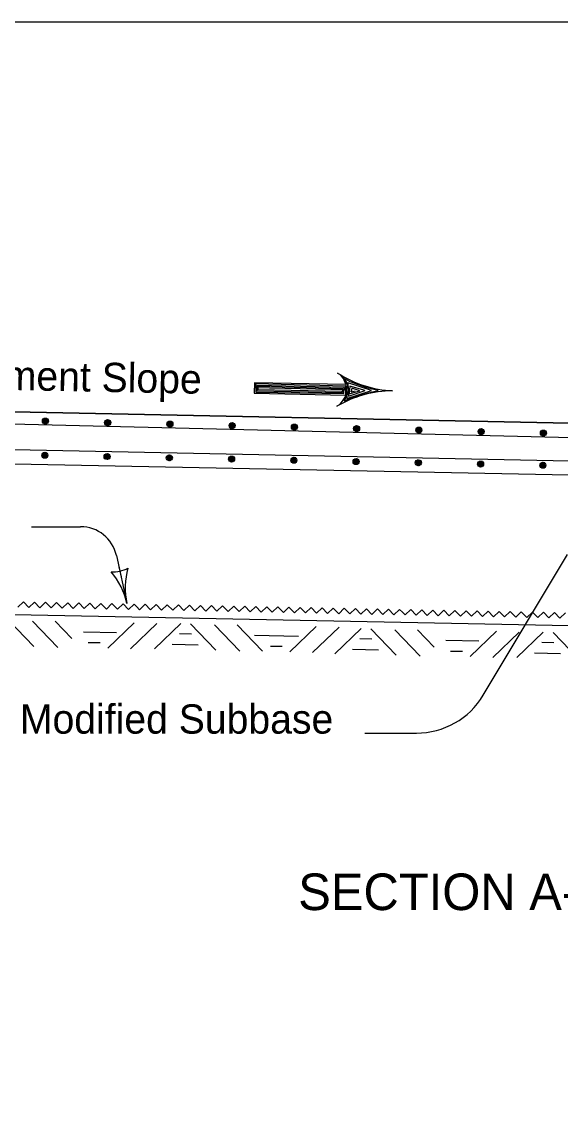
# Model space of a CAD drawing. Extents: x 9234 to 81668, y 5635 to 15999.
# Drawn here: x 17675 to 17970, y 9343 to 9944 of the extents above; entities that cross this region are included whole.
import ezdxf

# ---------------------------------------------------------------- set-up
doc = ezdxf.new("R2010")
doc.units = 0
for name, color, linetype in [('Level 61', 7, 'Continuous'), ('PS_BOLT', 7, 'Continuous'), ('PS_CONST', 7, 'Continuous'), ('PS_DIM', 7, 'Continuous')]:
    doc.layers.add(name, color=color, linetype=linetype)

msp = doc.modelspace()

# ---------------------------------------------------------------- linework, layer by layer
at = {"layer": 'Level 61'}
msp.add_lwpolyline([(17332.52, 9944.02), (20467.53, 9944.02), (20467.53, 7924.02), (17332.52, 7924.02)], close=True, dxfattribs=at)
at = {"layer": 'PS_BOLT'}
msp.add_line((18198.1, 9699.22), (17466.58, 9714.38), dxfattribs=at)
at = {"layer": 'PS_CONST'}
for p, q in [((17852.17, 9745.92), (17852.17, 9745.92)), ((17852.26, 9742.89), (17802.12, 9743.9)), ((17852.11, 9740.06), (17852.11, 9740.06)), ((17680.34, 9668.04), (17707.15, 9668.04)), ((17726.68, 9652.34), (17732.49, 9625.97)), ((17927.27, 9575.92), (17973.29, 9652.89)), ((17862.47, 9555.21), (17890.76, 9555.21))]:
    msp.add_line(p, q, dxfattribs=at)
for points in [[(17852.22, 9745.73), (17802.18, 9746.74), (17802.06, 9741.07), (17852.11, 9740.06), (17852.04, 9744.92), (17802.81, 9746.1), (17802.85, 9741.58), (17851.02, 9740.8), (17851.21, 9744.18), (17803.49, 9745.33), (17803.55, 9742.32), (17850.4, 9741.38), (17850.57, 9743.5), (17804.04, 9744.69), (17804.07, 9743), (17849.79, 9742.14)], [(17850.94, 9749.45), (17853, 9746.03), (17853.16, 9741.07), (17851.25, 9736.79), (17858.71, 9739.71), (17867.4, 9742.04), (17869.85, 9742.56), (17863.61, 9743.93), (17854.6, 9747.25), (17851.93, 9748.74), (17852.72, 9738.2), (17866.15, 9742.44), (17853.2, 9746.65), (17853.56, 9739.37), (17862.77, 9742.57), (17854.42, 9744.81), (17853.96, 9740.62), (17859.83, 9742.38), (17855.4, 9743.72), (17855.11, 9741.72), (17857.25, 9742.31)]]:
    msp.add_lwpolyline(points, dxfattribs=at)
for centre, radius, start, end in [((17841.88, 9743.1), 10.67, 300.56474, 57.13538), ((17880.75, 9803.26), 60.95, 237.1358, 267.16583), ((17878.3, 9681.43), 60.95, 90.53429, 120.56432), ((17707.15, 9648.04), 20, 12.43142, 90), ((17725.25, 9658.87), 15.52, 264.68499, 300.15169), ((17693.26, 9617.33), 40.18, 12.41834, 40.49083), ((17771.73, 9634.61), 40.18, 164.34585, 192.41834), ((17890.76, 9597.75), 42.54, 270, 329.12488)]:
    msp.add_arc(centre, radius, start, end, dxfattribs=at)
at = {"layer": 'PS_DIM'}
for p, q in [((18176.88, 9720.67), (17466.62, 9734.93)), ((17466.62, 9734.93), (18176.88, 9720.67)), ((17466.59, 9729.18), (18198.18, 9711.52)), ((17466.05, 9706.58), (18215.16, 9691.54)), ((17467.19, 9706.55), (18215.16, 9691.54)), ((17728.1, 9645.89), (17729.23, 9640.78)), ((17466.62, 9624.14), (18283.21, 9607.75)), ((17667.77, 9616.94), (17681.63, 9602.52)), ((17680.77, 9616.45), (17694.63, 9602.03)), ((17693.23, 9616.43), (17702.33, 9606.95)), ((17736.44, 9615.56), (17722.02, 9601.7)), ((17748.88, 9615.08), (17734.46, 9601.23)), ((17761.89, 9615.05), (17747.47, 9601.19)), ((17767.3, 9614.94), (17781.16, 9600.52)), ((17780.31, 9614.45), (17794.16, 9600.03)), ((17792.76, 9614.43), (17806.61, 9600.01)), ((17835.97, 9613.56), (17821.55, 9599.71)), ((17848.42, 9613.09), (17833.99, 9599.23)), ((17860.46, 9612.33), (17846.04, 9598.47)), ((17865.87, 9612.22), (17879.73, 9597.8)), ((17878.88, 9611.73), (17892.73, 9597.31)), ((17891.33, 9611.71), (17900.43, 9602.24)), ((17934.54, 9610.84), (17920.12, 9596.99)), ((17946.99, 9610.37), (17932.56, 9596.51)), ((17960, 9610.33), (17945.57, 9596.48)), ((17965.41, 9610.22), (17979.26, 9595.8))]:
    msp.add_line(p, q, dxfattribs=at)
for points in [[(17686.37, 9725.74), (17686.65, 9726.29), (17686.95, 9727.14), (17687.84, 9727.27), (17688.61, 9727.12), (17689.3, 9726.53), (17689.19, 9725.71), (17689.03, 9724.84), (17688.32, 9724.45), (17687.58, 9724.41), (17686.65, 9724.97), (17686.6, 9725.61), (17686.86, 9726.47), (17687.44, 9727.16), (17688.27, 9727.1), (17688.91, 9726.51), (17688.95, 9725.73), (17688.74, 9724.87), (17688.24, 9724.76), (17687.65, 9724.6), (17686.95, 9725.05), (17686.99, 9725.68), (17687.15, 9726.4), (17687.57, 9726.9), (17688.28, 9726.61), (17688.68, 9726.04), (17688.68, 9725.31), (17688.27, 9725.15), (17687.82, 9724.93), (17687.26, 9725.32), (17687.15, 9725.86), (17687.44, 9726.33), (17687.97, 9726.34), (17688.34, 9726.07), (17688.45, 9725.57), (17688.24, 9725.34), (17687.94, 9725.22), (17687.52, 9725.49), (17687.45, 9725.84), (17687.67, 9726.17), (17687.95, 9726.09), (17688.13, 9725.84), (17688.1, 9725.5), (17687.86, 9725.51), (17687.74, 9725.82)], [(17720.4, 9724.92), (17720.68, 9725.47), (17720.98, 9726.32), (17721.87, 9726.45), (17722.64, 9726.3), (17723.33, 9725.71), (17723.22, 9724.89), (17723.06, 9724.02), (17722.35, 9723.64), (17721.61, 9723.59), (17720.68, 9724.15), (17720.63, 9724.79), (17720.89, 9725.65), (17721.47, 9726.33), (17722.3, 9726.27), (17722.94, 9725.69), (17722.98, 9724.91), (17722.77, 9724.05), (17722.27, 9723.93), (17721.68, 9723.78), (17720.98, 9724.22), (17721.02, 9724.85), (17721.17, 9725.57), (17721.6, 9726.08), (17722.31, 9725.78), (17722.71, 9725.22), (17722.71, 9724.49), (17722.3, 9724.32), (17721.85, 9724.11), (17721.29, 9724.49), (17721.18, 9725.04), (17721.46, 9725.51), (17722, 9725.51), (17722.37, 9725.24), (17722.48, 9724.75), (17722.27, 9724.52), (17721.97, 9724.39), (17721.55, 9724.67), (17721.48, 9725.02), (17721.69, 9725.34), (17721.98, 9725.27), (17722.16, 9725.01), (17722.13, 9724.68), (17721.89, 9724.69), (17721.77, 9724.99)], [(17754.44, 9724.1), (17754.71, 9724.64), (17755.01, 9725.5), (17755.9, 9725.63), (17756.67, 9725.48), (17757.36, 9724.89), (17757.25, 9724.07), (17757.09, 9723.2), (17756.38, 9722.81), (17755.64, 9722.77), (17754.71, 9723.33), (17754.66, 9723.97), (17754.92, 9724.83), (17755.5, 9725.51), (17756.33, 9725.45), (17756.97, 9724.87), (17757.01, 9724.09), (17756.8, 9723.22), (17756.31, 9723.12), (17755.71, 9722.96), (17755.01, 9723.4), (17755.05, 9724.03), (17755.2, 9724.76), (17755.63, 9725.26), (17756.34, 9724.96), (17756.74, 9724.4), (17756.73, 9723.66), (17756.33, 9723.5), (17755.88, 9723.29), (17755.32, 9723.67), (17755.22, 9724.22), (17755.49, 9724.68), (17756.03, 9724.69), (17756.4, 9724.42), (17756.51, 9723.93), (17756.29, 9723.7), (17756, 9723.57), (17755.58, 9723.85), (17755.51, 9724.2), (17755.73, 9724.52), (17756.01, 9724.45), (17756.19, 9724.2), (17756.16, 9723.85), (17755.92, 9723.87), (17755.8, 9724.18)], [(17788.47, 9723.28), (17788.74, 9723.82), (17789.04, 9724.68), (17789.93, 9724.81), (17790.7, 9724.65), (17791.39, 9724.07), (17791.28, 9723.24), (17791.12, 9722.38), (17790.41, 9722), (17789.67, 9721.95), (17788.74, 9722.5), (17788.69, 9723.14), (17788.95, 9724), (17789.53, 9724.69), (17790.36, 9724.63), (17791, 9724.05), (17791.04, 9723.26), (17790.83, 9722.4), (17790.34, 9722.29), (17789.74, 9722.14), (17789.04, 9722.58), (17789.08, 9723.21), (17789.23, 9723.93), (17789.66, 9724.44), (17790.37, 9724.14), (17790.77, 9723.58), (17790.76, 9722.84), (17790.36, 9722.68), (17789.91, 9722.47), (17789.35, 9722.85), (17789.24, 9723.4), (17789.52, 9723.86), (17790.06, 9723.87), (17790.43, 9723.6), (17790.54, 9723.1), (17790.33, 9722.87), (17790.03, 9722.75), (17789.6, 9723.02), (17789.54, 9723.37), (17789.75, 9723.7), (17790.04, 9723.63), (17790.22, 9723.37), (17790.19, 9723.03), (17789.95, 9723.05), (17789.83, 9723.35)], [(17822.49, 9722.45), (17822.77, 9723), (17823.07, 9723.86), (17823.96, 9723.99), (17824.73, 9723.83), (17825.42, 9723.25), (17825.31, 9722.43), (17825.15, 9721.56), (17824.44, 9721.17), (17823.7, 9721.13), (17822.77, 9721.68), (17822.72, 9722.32), (17822.98, 9723.18), (17823.56, 9723.87), (17824.39, 9723.81), (17825.03, 9723.22), (17825.07, 9722.44), (17824.86, 9721.58), (17824.37, 9721.47), (17823.77, 9721.32), (17823.07, 9721.76), (17823.11, 9722.39), (17823.26, 9723.11), (17823.69, 9723.62), (17824.4, 9723.32), (17824.8, 9722.75), (17824.79, 9722.02), (17824.39, 9721.86), (17823.94, 9721.65), (17823.38, 9722.03), (17823.27, 9722.58), (17823.55, 9723.04), (17824.09, 9723.05), (17824.46, 9722.78), (17824.57, 9722.29), (17824.35, 9722.06), (17824.06, 9721.93), (17823.64, 9722.21), (17823.56, 9722.56), (17823.78, 9722.88), (17824.07, 9722.81), (17824.25, 9722.55), (17824.22, 9722.21), (17823.98, 9722.23), (17823.85, 9722.53)], [(17856.52, 9721.64), (17856.79, 9722.18), (17857.1, 9723.04), (17857.99, 9723.16), (17858.76, 9723.01), (17859.45, 9722.43), (17859.34, 9721.6), (17859.18, 9720.74), (17858.47, 9720.35), (17857.73, 9720.31), (17856.8, 9720.86), (17856.75, 9721.5), (17857, 9722.36), (17857.59, 9723.05), (17858.42, 9722.99), (17859.06, 9722.41), (17859.1, 9721.62), (17858.89, 9720.76), (17858.39, 9720.65), (17857.8, 9720.49), (17857.1, 9720.94), (17857.14, 9721.57), (17857.29, 9722.29), (17857.72, 9722.79), (17858.43, 9722.5), (17858.82, 9721.93), (17858.82, 9721.2), (17858.42, 9721.04), (17857.97, 9720.82), (17857.41, 9721.21), (17857.3, 9721.75), (17857.58, 9722.22), (17858.12, 9722.23), (17858.49, 9721.96), (17858.6, 9721.46), (17858.39, 9721.23), (17858.09, 9721.11), (17857.66, 9721.38), (17857.59, 9721.73), (17857.81, 9722.06), (17858.1, 9721.99), (17858.28, 9721.73), (17858.25, 9721.39), (17858.01, 9721.41), (17857.88, 9721.71)], [(17890.55, 9720.81), (17890.83, 9721.36), (17891.13, 9722.21), (17892.02, 9722.35), (17892.79, 9722.19), (17893.48, 9721.61), (17893.37, 9720.78), (17893.21, 9719.92), (17892.5, 9719.53), (17891.76, 9719.49), (17890.83, 9720.04), (17890.78, 9720.68), (17891.03, 9721.54), (17891.63, 9722.23), (17892.44, 9722.17), (17893.09, 9721.58), (17893.12, 9720.8), (17892.92, 9719.94), (17892.42, 9719.83), (17891.83, 9719.68), (17891.13, 9720.12), (17891.17, 9720.75), (17891.32, 9721.47), (17891.75, 9721.98), (17892.46, 9721.68), (17892.85, 9721.11), (17892.85, 9720.38), (17892.45, 9720.22), (17892, 9720.01), (17891.44, 9720.39), (17891.33, 9720.93), (17891.61, 9721.4), (17892.15, 9721.41), (17892.52, 9721.14), (17892.63, 9720.64), (17892.42, 9720.41), (17892.12, 9720.29), (17891.69, 9720.56), (17891.62, 9720.91), (17891.84, 9721.24), (17892.13, 9721.17), (17892.31, 9720.91), (17892.28, 9720.57), (17892.04, 9720.59), (17891.91, 9720.89)], [(17924.58, 9719.99), (17924.86, 9720.54), (17925.16, 9721.39), (17926.05, 9721.52), (17926.82, 9721.37), (17927.51, 9720.78), (17927.4, 9719.96), (17927.24, 9719.09), (17926.53, 9718.71), (17925.79, 9718.66), (17924.86, 9719.22), (17924.81, 9719.86), (17925.06, 9720.72), (17925.65, 9721.4), (17926.47, 9721.35), (17927.11, 9720.76), (17927.15, 9719.98), (17926.95, 9719.11), (17926.45, 9719.01), (17925.86, 9718.85), (17925.16, 9719.29), (17925.2, 9719.93), (17925.35, 9720.65), (17925.78, 9721.15), (17926.49, 9720.86), (17926.89, 9720.29), (17926.88, 9719.56), (17926.48, 9719.39), (17926.03, 9719.18), (17925.47, 9719.56), (17925.36, 9720.11), (17925.64, 9720.58), (17926.18, 9720.59), (17926.55, 9720.32), (17926.66, 9719.82), (17926.44, 9719.59), (17926.14, 9719.47), (17925.72, 9719.74), (17925.66, 9720.09), (17925.87, 9720.41), (17926.16, 9720.34), (17926.34, 9720.09), (17926.31, 9719.75), (17926.07, 9719.76), (17925.95, 9720.07)], [(17958.61, 9719.17), (17958.88, 9719.72), (17959.19, 9720.57), (17960.08, 9720.7), (17960.85, 9720.55), (17961.54, 9719.96), (17961.43, 9719.14), (17961.26, 9718.27), (17960.55, 9717.89), (17959.82, 9717.84), (17958.88, 9718.4), (17958.84, 9719.04), (17959.09, 9719.89), (17959.68, 9720.59), (17960.5, 9720.52), (17961.14, 9719.94), (17961.18, 9719.16), (17960.98, 9718.29), (17960.48, 9718.18), (17959.89, 9718.04), (17959.19, 9718.47), (17959.23, 9719.1), (17959.38, 9719.83), (17959.81, 9720.33), (17960.52, 9720.03), (17960.91, 9719.47), (17960.91, 9718.74), (17960.51, 9718.57), (17960.06, 9718.36), (17959.5, 9718.74), (17959.39, 9719.29), (17959.67, 9719.76), (17960.21, 9719.76), (17960.58, 9719.49), (17960.69, 9719), (17960.48, 9718.77), (17960.17, 9718.64), (17959.75, 9718.92), (17959.68, 9719.27), (17959.9, 9719.59), (17960.19, 9719.53), (17960.37, 9719.27), (17960.34, 9718.93), (17960.1, 9718.95), (17959.97, 9719.25)], [(17689.11, 9706.96), (17688.85, 9707.53), (17688.58, 9708.39), (17687.71, 9708.56), (17686.93, 9708.44), (17686.22, 9707.88), (17686.29, 9707.06), (17686.41, 9706.19), (17687.11, 9705.77), (17687.84, 9705.69), (17688.79, 9706.21), (17688.88, 9706.84), (17688.66, 9707.71), (17688.1, 9708.43), (17687.27, 9708.4), (17686.61, 9707.85), (17686.53, 9707.07), (17686.7, 9706.2), (17687.2, 9706.06), (17687.79, 9705.89), (17688.5, 9706.29), (17688.48, 9706.93), (17688.37, 9707.65), (17687.96, 9708.18), (17687.24, 9707.91), (17686.81, 9707.37), (17686.79, 9706.64), (17687.18, 9706.45), (17687.63, 9706.22), (17688.2, 9706.58), (17688.33, 9707.12), (17688.08, 9707.6), (17687.54, 9707.63), (17687.16, 9707.38), (17687.02, 9706.88), (17687.23, 9706.65), (17687.52, 9706.51), (17687.95, 9706.76), (17688.04, 9707.11), (17687.84, 9707.44), (17687.55, 9707.39), (17687.36, 9707.14), (17687.37, 9706.8), (17687.61, 9706.8), (17687.75, 9707.1)], [(17723.14, 9706.28), (17722.89, 9706.84), (17722.62, 9707.71), (17721.74, 9707.88), (17720.97, 9707.76), (17720.25, 9707.2), (17720.32, 9706.37), (17720.44, 9705.5), (17721.14, 9705.09), (17721.87, 9705.01), (17722.83, 9705.52), (17722.91, 9706.16), (17722.69, 9707.03), (17722.13, 9707.74), (17721.31, 9707.72), (17720.64, 9707.16), (17720.57, 9706.38), (17720.74, 9705.51), (17721.23, 9705.38), (17721.82, 9705.2), (17722.53, 9705.61), (17722.52, 9706.24), (17722.4, 9706.97), (17721.99, 9707.49), (17721.27, 9707.23), (17720.85, 9706.68), (17720.82, 9705.95), (17721.22, 9705.77), (17721.66, 9705.54), (17722.24, 9705.9), (17722.36, 9706.43), (17722.11, 9706.91), (17721.57, 9706.95), (17721.19, 9706.7), (17721.06, 9706.2), (17721.26, 9705.96), (17721.56, 9705.83), (17721.99, 9706.08), (17722.07, 9706.43), (17721.87, 9706.76), (17721.58, 9706.7), (17721.39, 9706.46), (17721.4, 9706.11), (17721.65, 9706.12), (17721.78, 9706.42)], [(17757.17, 9705.6), (17756.92, 9706.16), (17756.65, 9707.02), (17755.77, 9707.19), (17755, 9707.07), (17754.28, 9706.52), (17754.36, 9705.69), (17754.48, 9704.82), (17755.17, 9704.4), (17755.9, 9704.33), (17756.86, 9704.84), (17756.94, 9705.47), (17756.72, 9706.34), (17756.16, 9707.06), (17755.34, 9707.03), (17754.67, 9706.48), (17754.6, 9705.7), (17754.77, 9704.83), (17755.26, 9704.69), (17755.85, 9704.52), (17756.57, 9704.93), (17756.55, 9705.56), (17756.43, 9706.29), (17756.03, 9706.81), (17755.3, 9706.55), (17754.88, 9706), (17754.86, 9705.27), (17755.25, 9705.09), (17755.69, 9704.85), (17756.27, 9705.21), (17756.4, 9705.75), (17756.14, 9706.23), (17755.6, 9706.26), (17755.22, 9706.01), (17755.09, 9705.52), (17755.29, 9705.28), (17755.59, 9705.14), (17756.02, 9705.4), (17756.1, 9705.74), (17755.9, 9706.08), (17755.61, 9706.02), (17755.42, 9705.77), (17755.43, 9705.43), (17755.68, 9705.44), (17755.81, 9705.73)], [(17791.2, 9704.91), (17790.95, 9705.47), (17790.69, 9706.34), (17789.8, 9706.51), (17789.03, 9706.39), (17788.31, 9705.84), (17788.39, 9705.01), (17788.51, 9704.13), (17789.2, 9703.72), (17789.94, 9703.64), (17790.9, 9704.16), (17790.97, 9704.79), (17790.76, 9705.66), (17790.2, 9706.37), (17789.38, 9706.35), (17788.71, 9705.8), (17788.64, 9705.02), (17788.8, 9704.15), (17789.29, 9704.01), (17789.88, 9703.83), (17790.6, 9704.25), (17790.58, 9704.88), (17790.47, 9705.6), (17790.06, 9706.13), (17789.34, 9705.86), (17788.92, 9705.31), (17788.89, 9704.58), (17789.28, 9704.4), (17789.73, 9704.17), (17790.3, 9704.53), (17790.43, 9705.07), (17790.17, 9705.55), (17789.64, 9705.58), (17789.26, 9705.33), (17789.12, 9704.84), (17789.33, 9704.6), (17789.62, 9704.46), (17790.05, 9704.72), (17790.14, 9705.06), (17789.94, 9705.4), (17789.64, 9705.34), (17789.46, 9705.09), (17789.47, 9704.75), (17789.71, 9704.75), (17789.85, 9705.05)], [(17825.24, 9704.23), (17824.99, 9704.79), (17824.72, 9705.66), (17823.84, 9705.83), (17823.06, 9705.71), (17822.35, 9705.15), (17822.42, 9704.32), (17822.54, 9703.45), (17823.24, 9703.04), (17823.97, 9702.96), (17824.93, 9703.47), (17825.01, 9704.11), (17824.79, 9704.98), (17824.23, 9705.7), (17823.4, 9705.67), (17822.74, 9705.11), (17822.66, 9704.33), (17822.83, 9703.46), (17823.33, 9703.33), (17823.92, 9703.15), (17824.63, 9703.56), (17824.61, 9704.19), (17824.5, 9704.92), (17824.09, 9705.44), (17823.37, 9705.18), (17822.95, 9704.63), (17822.92, 9703.9), (17823.31, 9703.72), (17823.76, 9703.49), (17824.33, 9703.85), (17824.46, 9704.39), (17824.21, 9704.87), (17823.67, 9704.9), (17823.29, 9704.64), (17823.15, 9704.15), (17823.35, 9703.91), (17823.65, 9703.78), (17824.08, 9704.03), (17824.17, 9704.38), (17823.97, 9704.71), (17823.68, 9704.66), (17823.49, 9704.41), (17823.5, 9704.07), (17823.74, 9704.07), (17823.88, 9704.37)], [(17859.27, 9703.55), (17859.02, 9704.11), (17858.75, 9704.97), (17857.87, 9705.14), (17857.1, 9705.02), (17856.38, 9704.47), (17856.45, 9703.64), (17856.58, 9702.77), (17857.27, 9702.35), (17858, 9702.27), (17858.96, 9702.79), (17859.04, 9703.42), (17858.82, 9704.3), (17858.26, 9705.01), (17857.44, 9704.99), (17856.77, 9704.43), (17856.7, 9703.65), (17856.87, 9702.78), (17857.36, 9702.65), (17857.95, 9702.47), (17858.67, 9702.88), (17858.65, 9703.51), (17858.53, 9704.24), (17858.12, 9704.76), (17857.4, 9704.5), (17856.98, 9703.95), (17856.95, 9703.22), (17857.35, 9703.04), (17857.79, 9702.8), (17858.37, 9703.16), (17858.49, 9703.7), (17858.24, 9704.18), (17857.7, 9704.22), (17857.32, 9703.96), (17857.19, 9703.47), (17857.39, 9703.23), (17857.69, 9703.1), (17858.12, 9703.35), (17858.2, 9703.69), (17858, 9704.03), (17857.71, 9703.97), (17857.52, 9703.72), (17857.53, 9703.38), (17857.78, 9703.39), (17857.91, 9703.69)], [(17893.3, 9702.86), (17893.05, 9703.42), (17892.78, 9704.29), (17891.9, 9704.46), (17891.13, 9704.34), (17890.41, 9703.78), (17890.49, 9702.96), (17890.61, 9702.09), (17891.3, 9701.67), (17892.03, 9701.59), (17892.99, 9702.11), (17893.07, 9702.74), (17892.85, 9703.61), (17892.29, 9704.33), (17891.47, 9704.3), (17890.8, 9703.75), (17890.73, 9702.97), (17890.9, 9702.09), (17891.39, 9701.96), (17891.98, 9701.79), (17892.7, 9702.19), (17892.68, 9702.83), (17892.56, 9703.55), (17892.16, 9704.08), (17891.44, 9703.81), (17891.01, 9703.27), (17890.99, 9702.54), (17891.38, 9702.35), (17891.82, 9702.12), (17892.4, 9702.48), (17892.53, 9703.02), (17892.27, 9703.5), (17891.73, 9703.53), (17891.35, 9703.28), (17891.22, 9702.79), (17891.42, 9702.55), (17891.72, 9702.41), (17892.15, 9702.67), (17892.23, 9703.01), (17892.03, 9703.35), (17891.74, 9703.29), (17891.56, 9703.04), (17891.57, 9702.7), (17891.81, 9702.71), (17891.94, 9703)], [(17927.34, 9702.18), (17927.09, 9702.74), (17926.82, 9703.61), (17925.94, 9703.78), (17925.16, 9703.66), (17924.44, 9703.1), (17924.52, 9702.27), (17924.64, 9701.4), (17925.33, 9700.99), (17926.07, 9700.91), (17927.02, 9701.42), (17927.1, 9702.06), (17926.89, 9702.93), (17926.33, 9703.64), (17925.5, 9703.62), (17924.84, 9703.07), (17924.77, 9702.28), (17924.93, 9701.41), (17925.42, 9701.28), (17926.01, 9701.1), (17926.73, 9701.51), (17926.72, 9702.15), (17926.6, 9702.87), (17926.19, 9703.39), (17925.47, 9703.13), (17925.05, 9702.58), (17925.02, 9701.85), (17925.42, 9701.67), (17925.86, 9701.44), (17926.43, 9701.8), (17926.56, 9702.33), (17926.3, 9702.81), (17925.77, 9702.85), (17925.39, 9702.6), (17925.25, 9702.1), (17925.46, 9701.86), (17925.75, 9701.73), (17926.18, 9701.98), (17926.27, 9702.33), (17926.07, 9702.66), (17925.77, 9702.6), (17925.59, 9702.36), (17925.6, 9702.02), (17925.84, 9702.02), (17925.98, 9702.32)], [(17961.37, 9701.5), (17961.12, 9702.06), (17960.85, 9702.92), (17959.97, 9703.1), (17959.19, 9702.98), (17958.48, 9702.42), (17958.55, 9701.59), (17958.67, 9700.72), (17959.37, 9700.3), (17960.1, 9700.23), (17961.06, 9700.74), (17961.14, 9701.38), (17960.92, 9702.25), (17960.36, 9702.96), (17959.54, 9702.94), (17958.87, 9702.38), (17958.8, 9701.6), (17958.97, 9700.73), (17959.46, 9700.6), (17960.04, 9700.42), (17960.76, 9700.83), (17960.74, 9701.46), (17960.63, 9702.19), (17960.23, 9702.71), (17959.5, 9702.45), (17959.08, 9701.9), (17959.05, 9701.17), (17959.44, 9700.99), (17959.89, 9700.76), (17960.46, 9701.12), (17960.59, 9701.65), (17960.34, 9702.13), (17959.8, 9702.17), (17959.42, 9701.91), (17959.28, 9701.42), (17959.49, 9701.18), (17959.78, 9701.04), (17960.22, 9701.3), (17960.3, 9701.65), (17960.1, 9701.98), (17959.81, 9701.92), (17959.62, 9701.68), (17959.63, 9701.33), (17959.87, 9701.34), (17960.01, 9701.64)], [(17672.82, 9624.02), (17675.9, 9626.98), (17678.87, 9623.89), (17681.95, 9626.86), (17684.91, 9623.77), (17688, 9626.74), (17690.96, 9623.65), (17694.05, 9626.62), (17697.01, 9623.53), (17700.1, 9626.49), (17703.06, 9623.41), (17706.15, 9626.37), (17709.11, 9623.29), (17712.19, 9626.25), (17715.16, 9623.17), (17718.24, 9626.13), (17721.21, 9623.04), (17724.29, 9626.01), (17727.26, 9622.92), (17730.34, 9625.89), (17733.3, 9622.8), (17736.39, 9625.77), (17737.87, 9624.22)], [(17737.87, 9624.22), (17739.35, 9622.68), (17742.43, 9625.64), (17745.4, 9622.56), (17748.48, 9625.52), (17751.45, 9622.44), (17754.54, 9625.4), (17757.5, 9622.32), (17760.58, 9625.28), (17763.54, 9622.2), (17766.63, 9625.16), (17769.59, 9622.07), (17772.68, 9625.04), (17775.65, 9621.95), (17778.73, 9624.92), (17781.69, 9621.83), (17784.78, 9624.8), (17787.74, 9621.71), (17790.83, 9624.67), (17793.79, 9621.59), (17796.87, 9624.55), (17799.84, 9621.47), (17802.93, 9624.43), (17805.89, 9621.35), (17808.98, 9624.31), (17810.45, 9622.76)], [(17810.45, 9622.76), (17811.94, 9621.23), (17815.02, 9624.19), (17817.98, 9621.1), (17821.07, 9624.06), (17824.04, 9620.98), (17827.12, 9623.95), (17830.09, 9620.86), (17833.17, 9623.83), (17836.13, 9620.74), (17839.22, 9623.7), (17842.18, 9620.62), (17845.26, 9623.58), (17848.23, 9620.49), (17851.31, 9623.46), (17854.28, 9620.37), (17857.36, 9623.34), (17860.33, 9620.25), (17863.41, 9623.22), (17866.37, 9620.13), (17869.46, 9623.09), (17872.42, 9620.01), (17875.51, 9622.97), (17878.47, 9619.89), (17881.56, 9622.85), (17883.04, 9621.31)], [(17883.04, 9621.31), (17884.52, 9619.77), (17887.61, 9622.73), (17890.57, 9619.65), (17893.65, 9622.61), (17896.62, 9619.52), (17899.7, 9622.49), (17902.67, 9619.4), (17905.75, 9622.37), (17908.72, 9619.28), (17911.8, 9622.25), (17914.76, 9619.16), (17917.85, 9622.12), (17920.81, 9619.04), (17923.9, 9622), (17926.86, 9618.92), (17929.95, 9621.88), (17932.91, 9618.8), (17936, 9621.76), (17938.96, 9618.68), (17942.04, 9621.64), (17945.01, 9618.55), (17948.09, 9621.52), (17951.06, 9618.43), (17954.14, 9621.4), (17955.62, 9619.85)], [(17955.62, 9619.85), (17957.11, 9618.31), (17960.19, 9621.27), (17963.16, 9618.19), (17966.24, 9621.15), (17969.2, 9618.07), (17972.29, 9621.03)], [(17708.69, 9610.64), (17726.75, 9610.28)], [(17761.22, 9609.56), (17767.76, 9609.43)], [(17802.23, 9608.76), (17826.28, 9608.28)], [(17859.79, 9606.84), (17866.33, 9606.71)], [(17906.79, 9605.92), (17924.85, 9605.56)], [(17711.34, 9604.79), (17717.87, 9604.66)], [(17757.28, 9603.79), (17771.47, 9603.5)], [(17810.87, 9602.79), (17817.4, 9602.66)], [(17855.85, 9601.07), (17870.04, 9600.78)], [(17909.44, 9600.07), (17915.97, 9599.94)], [(17959.33, 9604.85), (17965.86, 9604.72)], [(17955.38, 9599.07), (17969.57, 9598.78)]]:
    msp.add_lwpolyline(points, dxfattribs=at)
for centre in [(17687.9, 9725.8), (17721.93, 9724.98), (17755.96, 9724.16), (17789.99, 9723.34), (17824.02, 9722.51), (17858.05, 9721.69), (17892.08, 9720.87), (17926.11, 9720.05), (17960.13, 9719.23), (17687.59, 9707.09), (17721.62, 9706.41), (17755.65, 9705.72), (17789.69, 9705.04), (17823.72, 9704.36), (17857.75, 9703.67), (17891.78, 9702.99), (17925.82, 9702.31), (17959.85, 9701.62)]:
    msp.add_circle(centre, 1.65, dxfattribs=at)

# ---------------------------------------------------------------- texts
at = {"layer": 'PS_CONST'}
msp.add_text('Normal Pavement Slope', height=16, rotation=358.85018, dxfattribs=at).set_placement((17541.38, 9745.36))
for s, height, p in [('Modified Subbase', 16, (17673.98, 9554.9)), ('SECTION A-A', 20, (17826.11, 9458.41))]:
    msp.add_text(s, height=height, dxfattribs=at).set_placement(p)

doc.saveas('drawing.dxf')
